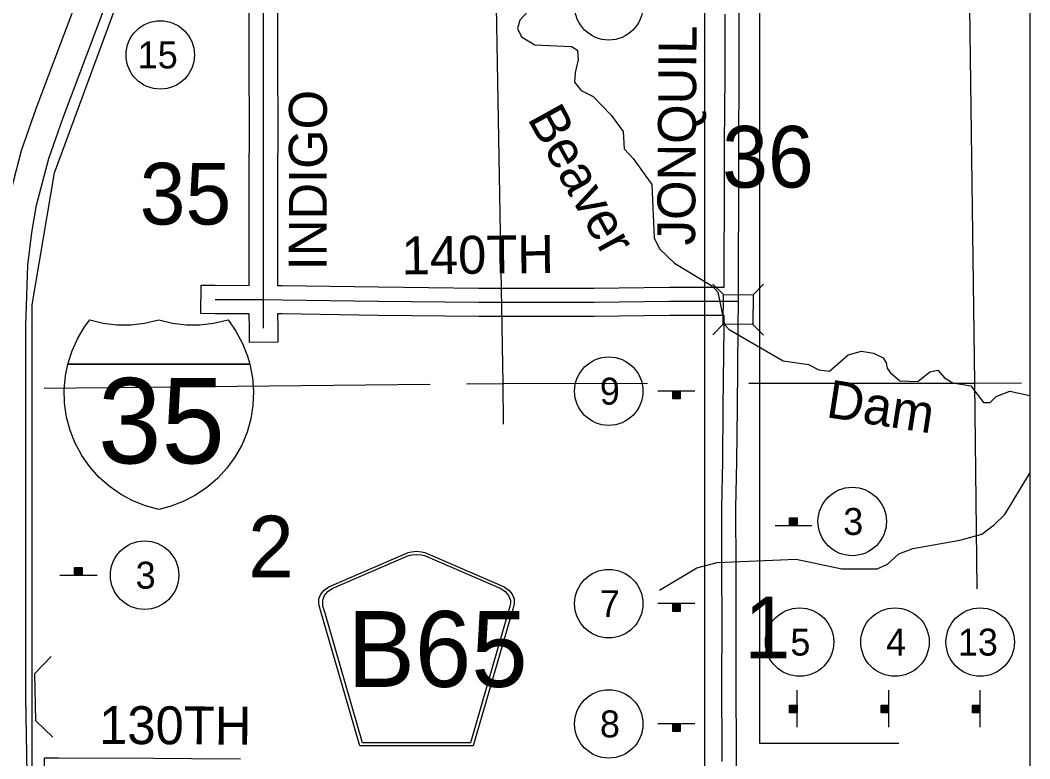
# Model space of a CAD drawing. Extents: x -2251611 to -2054719, y -2227156 to -2099355.
# Drawn here: x -2135345 to -2124096, y -2135199 to -2126976 of the extents above; entities that cross this region are included whole.
import ezdxf

# ---------------------------------------------------------------- set-up
doc = ezdxf.new("R2010")
doc.units = 0
for name, color, linetype in [('Default', 7, 'Continuous'), ('dsnTextFinalPlan', 7, 'Continuous'), ('dsnTextNote', 7, 'Continuous'), ('tdCoHydroRiver', 7, 'Continuous'), ('tdCoHydroTxtLg', 7, 'Continuous'), ('tdCoInt', 7, 'Continuous'), ('tdCoSecRdTxt', 7, 'Continuous'), ('tdCoSecRteBand', 7, 'Continuous'), ('tdCoSectLinePart', 7, 'Continuous'), ('tdCoSectNmbr', 7, 'Continuous'), ('tdCoShieldCoRte', 7, 'Continuous'), ('tdCoShieldInt', 7, 'Continuous'), ('tdCoStrucDivPri', 7, 'Continuous'), ('tdCoStrucSec', 7, 'Continuous'), ('tdCoSurfConc', 7, 'Continuous'), ('tdCoSurfGravel', 7, 'Continuous')]:
    doc.layers.add(name, color=color, linetype=linetype)

msp = doc.modelspace()

# ---------------------------------------------------------------- linework, layer by layer
at = {"layer": 'Default'}
for p, q in [((-2127105, -2135028), (-2127105, -2124556)), ((-2127722, -2125120), (-2127722, -2135863)), ((-2134962, -2128676), (-2134063, -2126236)), ((-2135211, -2130144), (-2134962, -2128676)), ((-2135211, -2139874), (-2135211, -2130144)), ((-2125555, -2135028), (-2127105, -2135028))]:
    msp.add_line(p, q, dxfattribs=at)
at = {"layer": 'dsnTextFinalPlan'}
for p, q in [((-2127827, -2131106), (-2128240, -2131106)), ((-2128074, -2131112), (-2127990, -2131112)), ((-2127990, -2131116), (-2128074, -2131116)), ((-2128074, -2131120), (-2127990, -2131120)), ((-2127990, -2131124), (-2128074, -2131124)), ((-2128074, -2131127), (-2127990, -2131127)), ((-2127990, -2131131), (-2128074, -2131131)), ((-2128074, -2131136), (-2127990, -2131136)), ((-2127990, -2131140), (-2128074, -2131140)), ((-2128074, -2131143), (-2127990, -2131143)), ((-2127990, -2131148), (-2128074, -2131148)), ((-2128074, -2131153), (-2127990, -2131153)), ((-2127990, -2131160), (-2128074, -2131160)), ((-2128074, -2131163), (-2127990, -2131163)), ((-2127990, -2131169), (-2128074, -2131170)), ((-2128074, -2131173), (-2127990, -2131173)), ((-2127990, -2131177), (-2128074, -2131177)), ((-2128074, -2131181), (-2127990, -2131181)), ((-2127990, -2131186), (-2128074, -2131186)), ((-2126772, -2132520), (-2126689, -2132520)), ((-2126689, -2132525), (-2126772, -2132525)), ((-2126772, -2132529), (-2126689, -2132529)), ((-2126689, -2132533), (-2126772, -2132533)), ((-2126772, -2132537), (-2126689, -2132536)), ((-2126689, -2132543), (-2126772, -2132543)), ((-2126935, -2132600), (-2126523, -2132600)), ((-2126772, -2132546), (-2126689, -2132546)), ((-2126689, -2132553), (-2126772, -2132553)), ((-2126772, -2132558), (-2126689, -2132558)), ((-2126689, -2132563), (-2126772, -2132563)), ((-2126772, -2132567), (-2126689, -2132567)), ((-2126689, -2132570), (-2126772, -2132570)), ((-2126772, -2132576), (-2126689, -2132576)), ((-2126689, -2132579), (-2126772, -2132579)), ((-2126772, -2132582), (-2126689, -2132582)), ((-2126689, -2132586), (-2126772, -2132586)), ((-2126772, -2132590), (-2126689, -2132590)), ((-2126689, -2132594), (-2126772, -2132594)), ((-2134739, -2133076), (-2134655, -2133076)), ((-2134655, -2133080), (-2134739, -2133080)), ((-2134739, -2133084), (-2134655, -2133084)), ((-2134655, -2133088), (-2134739, -2133088)), ((-2134739, -2133092), (-2134655, -2133092)), ((-2134655, -2133098), (-2134739, -2133098)), ((-2134739, -2133101), (-2134655, -2133101)), ((-2134902, -2133155), (-2134489, -2133155)), ((-2134655, -2133108), (-2134739, -2133108)), ((-2134739, -2133114), (-2134655, -2133114)), ((-2134655, -2133118), (-2134739, -2133119)), ((-2134739, -2133122), (-2134655, -2133122)), ((-2134655, -2133126), (-2134739, -2133126)), ((-2134739, -2133131), (-2134655, -2133131)), ((-2134655, -2133134), (-2134739, -2133134)), ((-2134739, -2133137), (-2134655, -2133137)), ((-2134655, -2133141), (-2134739, -2133141)), ((-2134739, -2133145), (-2134655, -2133145)), ((-2134655, -2133149), (-2134739, -2133149)), ((-2127827, -2133472), (-2128240, -2133472)), ((-2128074, -2133478), (-2127990, -2133478)), ((-2127990, -2133482), (-2128074, -2133482)), ((-2128074, -2133486), (-2127990, -2133486)), ((-2127990, -2133490), (-2128074, -2133490)), ((-2128074, -2133494), (-2127990, -2133494)), ((-2127990, -2133497), (-2128074, -2133497)), ((-2128074, -2133502), (-2127990, -2133502)), ((-2127990, -2133506), (-2128074, -2133506)), ((-2128074, -2133509), (-2127990, -2133509)), ((-2127990, -2133514), (-2128074, -2133514)), ((-2128074, -2133519), (-2127990, -2133519)), ((-2127990, -2133526), (-2128074, -2133526)), ((-2128074, -2133529), (-2127990, -2133529)), ((-2127990, -2133535), (-2128074, -2133536)), ((-2128074, -2133539), (-2127990, -2133539)), ((-2127990, -2133544), (-2128074, -2133544)), ((-2128074, -2133547), (-2127990, -2133547)), ((-2127990, -2133552), (-2128074, -2133552)), ((-2126687, -2134848), (-2126687, -2134436)), ((-2125667, -2134848), (-2125667, -2134436)), ((-2124650, -2134848), (-2124650, -2134436)), ((-2126767, -2134685), (-2126767, -2134601)), ((-2126762, -2134601), (-2126762, -2134685)), ((-2126759, -2134685), (-2126759, -2134601)), ((-2126754, -2134601), (-2126754, -2134685)), ((-2126751, -2134685), (-2126751, -2134601)), ((-2126744, -2134601), (-2126744, -2134685)), ((-2126741, -2134685), (-2126741, -2134601)), ((-2126734, -2134601), (-2126734, -2134685)), ((-2126729, -2134685), (-2126729, -2134601)), ((-2126724, -2134601), (-2126724, -2134685)), ((-2126721, -2134685), (-2126721, -2134601)), ((-2126717, -2134601), (-2126717, -2134685)), ((-2126712, -2134685), (-2126712, -2134601)), ((-2126709, -2134601), (-2126709, -2134685)), ((-2126705, -2134685), (-2126705, -2134601)), ((-2126701, -2134601), (-2126701, -2134685)), ((-2126697, -2134685), (-2126697, -2134601)), ((-2126693, -2134601), (-2126693, -2134685)), ((-2125747, -2134685), (-2125747, -2134601)), ((-2125743, -2134601), (-2125743, -2134685)), ((-2125739, -2134685), (-2125739, -2134601)), ((-2125734, -2134601), (-2125734, -2134685)), ((-2125731, -2134685), (-2125731, -2134601)), ((-2125725, -2134601), (-2125725, -2134685)), ((-2125721, -2134685), (-2125721, -2134601)), ((-2125715, -2134601), (-2125715, -2134685)), ((-2125709, -2134685), (-2125709, -2134601)), ((-2125705, -2134601), (-2125704, -2134685)), ((-2125701, -2134685), (-2125701, -2134601)), ((-2125697, -2134601), (-2125697, -2134685)), ((-2125692, -2134685), (-2125692, -2134601)), ((-2125689, -2134601), (-2125689, -2134685)), ((-2125686, -2134685), (-2125686, -2134601)), ((-2125682, -2134601), (-2125682, -2134685)), ((-2125678, -2134685), (-2125678, -2134601)), ((-2125674, -2134601), (-2125674, -2134685)), ((-2124730, -2134685), (-2124730, -2134601)), ((-2124725, -2134601), (-2124725, -2134685)), ((-2124722, -2134685), (-2124722, -2134601)), ((-2124717, -2134601), (-2124717, -2134685)), ((-2124714, -2134685), (-2124714, -2134601)), ((-2124708, -2134601), (-2124707, -2134685)), ((-2124704, -2134685), (-2124704, -2134601)), ((-2124698, -2134601), (-2124698, -2134685)), ((-2124692, -2134685), (-2124692, -2134601)), ((-2124687, -2134601), (-2124687, -2134685)), ((-2124684, -2134685), (-2124684, -2134601)), ((-2124680, -2134601), (-2124680, -2134685)), ((-2124675, -2134685), (-2124675, -2134601)), ((-2124672, -2134601), (-2124672, -2134685)), ((-2124668, -2134685), (-2124668, -2134601)), ((-2124665, -2134601), (-2124665, -2134685)), ((-2124661, -2134685), (-2124661, -2134601)), ((-2124656, -2134601), (-2124656, -2134685)), ((-2127827, -2134811), (-2128240, -2134811)), ((-2128074, -2134817), (-2127990, -2134817)), ((-2127990, -2134822), (-2128074, -2134822)), ((-2128074, -2134826), (-2127990, -2134826)), ((-2127990, -2134829), (-2128074, -2134829)), ((-2128074, -2134833), (-2127990, -2134833)), ((-2127990, -2134836), (-2128074, -2134836)), ((-2128074, -2134841), (-2127990, -2134841)), ((-2127990, -2134845), (-2128074, -2134845)), ((-2128074, -2134848), (-2127990, -2134848)), ((-2127990, -2134853), (-2128074, -2134853)), ((-2128074, -2134859), (-2127990, -2134859)), ((-2127990, -2134865), (-2128074, -2134865)), ((-2128074, -2134869), (-2127990, -2134868)), ((-2127990, -2134875), (-2128074, -2134875)), ((-2128074, -2134878), (-2127990, -2134878)), ((-2127990, -2134883), (-2128074, -2134883)), ((-2128074, -2134886), (-2127990, -2134886)), ((-2127990, -2134891), (-2128074, -2134891))]:
    msp.add_line(p, q, dxfattribs=at)
for points in [[(-2128074, -2131107), (-2127990, -2131107), (-2127990, -2131192), (-2128074, -2131192)], [(-2126689, -2132599), (-2126773, -2132599), (-2126773, -2132515), (-2126689, -2132515)], [(-2134655, -2133154), (-2134740, -2133154), (-2134740, -2133070), (-2134655, -2133070)], [(-2128074, -2133473), (-2127990, -2133473), (-2127990, -2133558), (-2128074, -2133558)], [(-2126688, -2134601), (-2126688, -2134686), (-2126773, -2134686), (-2126773, -2134601)], [(-2125669, -2134601), (-2125669, -2134686), (-2125753, -2134686), (-2125753, -2134601)], [(-2124652, -2134601), (-2124652, -2134686), (-2124736, -2134686), (-2124736, -2134601)], [(-2128074, -2134813), (-2127990, -2134813), (-2127990, -2134897), (-2128074, -2134897)]]:
    msp.add_lwpolyline(points, close=True, dxfattribs=at)
at = {"layer": 'dsnTextNote'}
msp.add_lwpolyline([(-2138305, -2118110), (-2124096, -2118110), (-2124096, -2144316), (-2146960, -2144316), (-2146960, -2118110), (-2138305, -2118110)], dxfattribs=at)
for centre in [(-2128787, -2126816), (-2133785, -2127363), (-2128787, -2131106), (-2126075, -2132557), (-2133959, -2133155), (-2128787, -2133472), (-2126661, -2133900), (-2125598, -2133900), (-2124649, -2133900), (-2128787, -2134811)]:
    msp.add_circle(centre, 381, dxfattribs=at)
at = {"layer": 'tdCoHydroRiver'}
for points in [[(-2129604, -2126785), (-2129778, -2126977), (-2129803, -2127069), (-2129761, -2127161), (-2129611, -2127252), (-2129203, -2127268), (-2129136, -2127309), (-2129127, -2127417), (-2129160, -2127559), (-2129169, -2127667), (-2129093, -2127759), (-2128960, -2127825), (-2128759, -2128033), (-2128626, -2128216), (-2128617, -2128408), (-2128517, -2128516), (-2128308, -2128807), (-2128281, -2129398), (-2128223, -2129523), (-2128056, -2129681), (-2127630, -2129939), (-2127572, -2130005), (-2127496, -2130363), (-2127446, -2130421), (-2126845, -2130770), (-2126561, -2130811), (-2126445, -2130869), (-2126328, -2130885), (-2126120, -2130702), (-2125970, -2130660), (-2125837, -2130684), (-2125728, -2130734), (-2125695, -2130792), (-2125686, -2130851), (-2125653, -2130900), (-2125544, -2130992), (-2125344, -2131000), (-2125211, -2130891), (-2125120, -2130874), (-2125045, -2130957), (-2124953, -2131015), (-2124753, -2131048), (-2124611, -2131231), (-2124536, -2131231), (-2124469, -2131164), (-2124319, -2131106), (-2124096, -2131153)], [(-2128222, -2133323), (-2127806, -2133072), (-2127581, -2133013), (-2126698, -2132978), (-2126189, -2133085), (-2125798, -2133084), (-2125681, -2133034), (-2125557, -2132917), (-2125398, -2132858), (-2124874, -2132765), (-2124632, -2132698), (-2124491, -2132589), (-2124374, -2132481), (-2124096, -2132021)]]:
    msp.add_lwpolyline(points, dxfattribs=at)
at = {"layer": 'tdCoInt'}
for points in [[(-2135593, -2137727), (-2135583, -2135365), (-2135600, -2134511), (-2135598, -2130378), (-2135576, -2129678), (-2135530, -2129293), (-2135473, -2128972), (-2135332, -2128427), (-2135169, -2127960), (-2134429, -2125998), (-2134077, -2125064)], [(-2135276, -2137727), (-2135266, -2135362), (-2135283, -2134508), (-2135281, -2130380), (-2135260, -2129704), (-2135217, -2129339), (-2135162, -2129034), (-2135027, -2128516), (-2134872, -2128071), (-2134131, -2126106), (-2133742, -2125075), (-2133739, -2125066)]]:
    msp.add_lwpolyline(points, dxfattribs=at)
at = {"layer": 'tdCoSecRteBand'}
for points in [[(-2127522, -2135228), (-2127522, -2135130), (-2127528, -2134366), (-2127528, -2134365), (-2127528, -2134365), (-2127525, -2133698), (-2127526, -2133077), (-2127529, -2132410), (-2127529, -2132408), (-2127529, -2132406), (-2127518, -2131886), (-2127512, -2131287), (-2127503, -2130395), (-2127502, -2130264), (-2128109, -2130264), (-2128951, -2130275), (-2128952, -2130275), (-2128953, -2130275), (-2130235, -2130275), (-2130236, -2130275), (-2130236, -2130275), (-2131361, -2130262), (-2131362, -2130262), (-2131362, -2130262), (-2132429, -2130246), (-2132478, -2130246), (-2132475, -2130402), (-2132473, -2130561), (-2132790, -2130565), (-2132792, -2130407), (-2132795, -2130245), (-2132795, -2130245), (-2133173, -2130244), (-2133331, -2130243), (-2133330, -2129926), (-2133172, -2129927), (-2132794, -2129928), (-2132794, -2129364), (-2132795, -2128756), (-2132795, -2128756), (-2132795, -2128755), (-2132791, -2128157), (-2132794, -2127488), (-2132794, -2127488), (-2132794, -2127488), (-2132795, -2126842)], [(-2132478, -2126842), (-2132477, -2127487), (-2132474, -2128156), (-2132474, -2128157), (-2132474, -2128158), (-2132478, -2128756), (-2132477, -2129364), (-2132477, -2129364), (-2132477, -2129364), (-2132477, -2129929), (-2132427, -2129929), (-2132426, -2129929), (-2132425, -2129929), (-2131358, -2129945), (-2130234, -2129958)], [(-2130234, -2129958), (-2128954, -2129958), (-2128112, -2129948), (-2128111, -2129948), (-2128110, -2129948), (-2127501, -2129948), (-2127501, -2129947), (-2127500, -2129806), (-2127500, -2129649), (-2127500, -2129649), (-2127500, -2129648), (-2127498, -2129021), (-2127496, -2128349), (-2127496, -2128349), (-2127496, -2128349), (-2127492, -2127599), (-2127492, -2127473), (-2127491, -2126909)], [(-2135078, -2135504), (-2135076, -2135187), (-2134918, -2135188), (-2133858, -2135193), (-2133436, -2135195), (-2133435, -2135195), (-2133435, -2135195), (-2132892, -2135201)]]:
    msp.add_lwpolyline(points, dxfattribs=at)
at = {"layer": 'tdCoSectLinePart'}
for points in [[(-2124784, -2125721), (-2124714, -2131016)], [(-2130056, -2125978), (-2129969, -2131021)], [(-2135080, -2131074), (-2130779, -2131029)], [(-2130371, -2131025), (-2129969, -2131021)], [(-2129969, -2131021), (-2128357, -2131019)], [(-2129969, -2131021), (-2129965, -2131472)], [(-2127226, -2131018), (-2124714, -2131016)], [(-2124714, -2131016), (-2124190, -2131015)], [(-2124714, -2131016), (-2124687, -2133306)]]:
    msp.add_lwpolyline(points, dxfattribs=at)
at = {"layer": 'tdCoShieldCoRte'}
for points in [[(-2131562, -2135055), (-2131995, -2133561), (-2132015, -2133492), (-2132019, -2133461), (-2132019, -2133419), (-2131996, -2133365), (-2131958, -2133320), (-2131908, -2133285), (-2131024, -2132903), (-2130985, -2132894), (-2130930, -2132889), (-2130875, -2132894), (-2130835, -2132903), (-2129952, -2133285), (-2129901, -2133320), (-2129863, -2133365), (-2129840, -2133419), (-2129840, -2133461), (-2129844, -2133492), (-2129865, -2133561), (-2130297, -2135055)], [(-2131531, -2135021), (-2131952, -2133568), (-2131972, -2133501), (-2131975, -2133472), (-2131975, -2133432), (-2131954, -2133380), (-2131917, -2133337), (-2131868, -2133303), (-2131020, -2132936), (-2130982, -2132928), (-2130930, -2132923), (-2130877, -2132928), (-2130839, -2132936), (-2129991, -2133303), (-2129942, -2133337), (-2129905, -2133380), (-2129884, -2133432), (-2129884, -2133472), (-2129888, -2133501), (-2129907, -2133568), (-2130328, -2135021)]]:
    msp.add_lwpolyline(points, close=True, dxfattribs=at)
at = {"layer": 'tdCoShieldInt'}
msp.add_line((-2134797, -2130805), (-2132804, -2130805), dxfattribs=at)
for points in [[(-2133800, -2132423), (-2133949, -2132383), (-2134092, -2132326), (-2134228, -2132253), (-2134354, -2132165), (-2134469, -2132063), (-2134571, -2131948), (-2134659, -2131821), (-2134732, -2131686), (-2134789, -2131543), (-2134828, -2131394), (-2134850, -2131241), (-2134854, -2131087), (-2134840, -2130934), (-2134814, -2130805), (-2134767, -2130659), (-2134704, -2130518), (-2134624, -2130386), (-2134570, -2130313), (-2134421, -2130349), (-2134268, -2130368), (-2134114, -2130369), (-2133961, -2130351), (-2133800, -2130313), (-2133650, -2130349), (-2133497, -2130368), (-2133343, -2130369), (-2133190, -2130351), (-2133029, -2130313), (-2132941, -2130439), (-2132868, -2130575), (-2132811, -2130718), (-2132786, -2130805), (-2132757, -2130957), (-2132745, -2131110), (-2132752, -2131264), (-2132776, -2131416), (-2132818, -2131564), (-2132877, -2131706), (-2132953, -2131841), (-2133043, -2131965), (-2133147, -2132079), (-2133264, -2132179), (-2133392, -2132265), (-2133529, -2132336), (-2133673, -2132390)], [(-2134814, -2130805), (-2134767, -2130659), (-2134704, -2130518), (-2134624, -2130386), (-2134570, -2130313), (-2134421, -2130349), (-2134268, -2130368), (-2134114, -2130369), (-2133961, -2130351), (-2133800, -2130313), (-2133650, -2130349), (-2133497, -2130368), (-2133343, -2130369), (-2133190, -2130351), (-2133029, -2130313), (-2132941, -2130439), (-2132868, -2130575), (-2132811, -2130718), (-2132786, -2130805)], [(-2133800, -2132423), (-2133949, -2132383), (-2134092, -2132326), (-2134228, -2132253), (-2134354, -2132165), (-2134469, -2132063), (-2134571, -2131948), (-2134659, -2131821), (-2134732, -2131686), (-2134789, -2131543), (-2134828, -2131394), (-2134850, -2131241), (-2134854, -2131087), (-2134840, -2130934), (-2134814, -2130805), (-2132786, -2130805), (-2132757, -2130957), (-2132745, -2131110), (-2132752, -2131264), (-2132776, -2131416), (-2132818, -2131564), (-2132877, -2131706), (-2132953, -2131841), (-2133043, -2131965), (-2133147, -2132079), (-2133264, -2132179), (-2133392, -2132265), (-2133529, -2132336), (-2133673, -2132390)]]:
    msp.add_lwpolyline(points, close=True, dxfattribs=at)
at = {"layer": 'tdCoStrucDivPri'}
msp.add_lwpolyline([(-2134982, -2134960), (-2135172, -2134777), (-2135183, -2134249), (-2135000, -2134059)], dxfattribs=at)
at = {"layer": 'tdCoStrucSec'}
for p, q in [((-2127510, -2130031), (-2127626, -2129914)), ((-2127179, -2130033), (-2127062, -2129916)), ((-2127511, -2130362), (-2127629, -2130478)), ((-2127181, -2130363), (-2127065, -2130481))]:
    msp.add_line(p, q, dxfattribs=at)
msp.add_lwpolyline([(-2127511, -2130362), (-2127510, -2130031), (-2127179, -2130033), (-2127181, -2130363)], close=True, dxfattribs=at)
at = {"layer": 'tdCoSurfConc'}
for points in [[(-2127334, -2127473), (-2127333, -2126909), (-2127333, -2126260), (-2127334, -2126137), (-2127338, -2125893), (-2127336, -2125784), (-2127333, -2125587), (-2127333, -2125416), (-2127333, -2125176), (-2127332, -2125051), (-2127330, -2124825)], [(-2127364, -2135387), (-2127364, -2135130), (-2127369, -2134365), (-2127367, -2133699), (-2127368, -2133076), (-2127371, -2132409), (-2127360, -2131889), (-2127354, -2131288), (-2127344, -2130396), (-2127343, -2130106), (-2127342, -2129807), (-2127342, -2129649), (-2127339, -2129021), (-2127338, -2128350), (-2127334, -2127600), (-2127334, -2127473)]]:
    msp.add_lwpolyline(points, dxfattribs=at)
at = {"layer": 'tdCoSurfGravel'}
msp.add_line((-2133172, -2130085), (-2132636, -2130087), dxfattribs=at)
for points in [[(-2132636, -2130093), (-2132636, -2130087), (-2132635, -2129973), (-2132635, -2129364), (-2132636, -2128756), (-2132633, -2128157), (-2132635, -2127488), (-2132636, -2126842), (-2132639, -2126234), (-2132640, -2125635), (-2132642, -2125019), (-2132642, -2124881), (-2132639, -2124806)], [(-2132636, -2130087), (-2132636, -2130087), (-2132427, -2130088), (-2131360, -2130103), (-2130235, -2130116), (-2128953, -2130116), (-2128110, -2130106), (-2127343, -2130106)], [(-2132634, -2130404), (-2132636, -2130218), (-2132636, -2130093)]]:
    msp.add_lwpolyline(points, dxfattribs=at)

# ---------------------------------------------------------------- texts
at = {"layer": 'dsnTextNote'}
for s, p in [('15', (-2134036, -2127513)), ('9', (-2128887, -2131256)), ('3', (-2126175, -2132707)), ('3', (-2134059, -2133305)), ('7', (-2128887, -2133622)), ('5', (-2126764, -2134050)), ('4', (-2125698, -2134050)), ('13', (-2124898, -2134050)), ('8', (-2128886, -2134961))]:
    msp.add_text(s, height=300, dxfattribs=at).set_placement(p)
at = {"layer": 'tdCoHydroTxtLg'}
for s, rotation, p in [('Beaver', 298.8741, (-2129700, -2128070)), ('Dam', 351.1495, (-2126376, -2131394))]:
    msp.add_text(s, height=422.4, rotation=rotation, dxfattribs=at).set_placement(p)
at = {"layer": 'tdCoSecRdTxt'}
for s, rotation, p in [('JONQUIL', 89.5797, (-2127826, -2129484)), ('INDIGO', 89.9539, (-2131930, -2129761)), ('140TH', 0.6404, (-2131092, -2129808)), ('130TH', 359.7361, (-2134466, -2135034))]:
    msp.add_text(s, height=422.4, rotation=rotation, dxfattribs=at).set_placement(p)
at = {"layer": 'tdCoSectNmbr'}
for s, height, rotation, p in [('36', 686.4, 0.0209, (-2127524, -2128840)), ('35', 686.4, 0.02, (-2134014, -2129251)), ('2', 686, 0.02, (-2132806, -2133179)), ('1', 686, 0.0208, (-2127275, -2134082))]:
    msp.add_text(s, height=height, rotation=rotation, dxfattribs=at).set_placement(p)
at = {"layer": 'tdCoShieldCoRte'}
msp.add_text('B65', height=844.8, dxfattribs=at).set_placement((-2131701, -2134399))
at = {"layer": 'tdCoShieldInt'}
msp.add_text('35', height=950.4, dxfattribs=at).set_placement((-2134478, -2131910))

doc.saveas('drawing.dxf')
